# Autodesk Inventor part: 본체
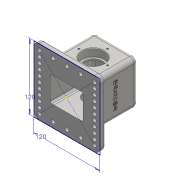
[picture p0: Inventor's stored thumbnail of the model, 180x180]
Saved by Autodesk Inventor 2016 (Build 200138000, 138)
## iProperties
Created: 2018-11
Part Number: 본체
Material: 일반
Document SubType Name: Modeling
Designer: 605-04
Density: 1 g/cm^3
Appearance: 기본값
Author: 605-04
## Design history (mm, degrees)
sketch "스케치1"
  geometry: L1 (-60, 60)-(60, 60); L2 (60, 60)-(60, -60); L3 (60, -60)-(-60, -60); L4 (-60, -60)-(-60, 60); L5 (-60, 60)-(60, -60); L6 (60, 60)-(-60, -60); L7 (-60, 60)-(60, 60); L8 (60, 60)-(60, -60); L9 (60, -60)-(-60, -60); L10 (-60, -60)-(-60, 60); L11 (-60, 60)-(60, -60); L12 (60, 60)-(-60, -60); 1 further point
  constraints: 24 end point, 4 midpoint, 4 parallel, 2 horizontal, 2 perpendicular
  dimensions: "d90" = 120 distance of L2.end L3.end; "d91" = 120 distance of L1.end L2.end
extrude "돌출1" new body sketch "스케치1" distance "d1" = 10; taper "d2" = 0 deg
sketch "스케치2"
  geometry: L1 (40, -40)-(-40, -40); L2 (-40, -40)-(-40, 40); L3 (-40, 40)-(40, 40); L4 (40, 40)-(40, -40); L5 (40, -40)-(-40, 40); L6 (-40, -40)-(40, 40); 1 further point
  constraints: 12 end point, 2 midpoint, 2 parallel, 1 horizontal, 1 perpendicular
  dimensions: "d3" = 80 distance of L2.end L3.end; "d85" = 80 distance of L1.end L2.end
extrude "돌출2" join sketch "스케치2" distance "d4" = 80; taper "d5" = 0 deg
sketch "스케치3"
  geometry: C1 r 7.5 at (0, 0); 1 further point
  constraints: 1 centre point, 1 coincident
  dimensions: "d6" = 15 diameter of C1
extrude "돌출3" join sketch "스케치3" distance "d7" = 5; taper "d8" = 0 deg
sketch "스케치5"
  geometry: L1 (-30, -23)-(30, -23); L2 (30, -23)-(30, 23); L3 (30, 23)-(-30, 23); L4 (-30, 23)-(-30, -23); L5 (-30, -23)-(30, 23); L6 (30, -23)-(-30, 23); 1 further point
  constraints: 12 end point, 2 midpoint, 2 parallel, 1 horizontal, 1 perpendicular
  dimensions: "d9" = 46 distance of L1.end L2.end; "d26" = 60 distance of L2.end L3.end
extrude "돌출4" cut sketch "스케치5" distance "d10" = 80; taper "d11" = 0 deg
sketch "스케치6"
  geometry: L1 (100, -10)-(-20, -10) reference; C1 r 20 at (40, 38); 1 further point
  constraints: 1 centre point
  dimensions: "d12" = 48 distance from line of L1 C1.centre; "d13" = 40 diameter of C1
extrude "돌출5" cut sketch "스케치6" distance "d14" = 14; taper "d15" = 0 deg
sketch "스케치7"
  geometry: C1 r 16.5 at (0, 0); 1 further point
  constraints: 1 centre point
  dimensions: "d16" = 33 diameter of C1
extrude "돌출6" cut sketch "스케치7" distance "d17" = 3; taper "d18" = 0 deg
sketch "스케치8"
  geometry: 2 further points
  constraints: 1 coincident
hole "구멍1" sketch "스케치8" at (0, 0) diameter "d19" = 4.917; stored, may be unused: countersink angle "d23" = 90 deg, drill point angle "d25" = 118 deg; dims "d20" = 12, "d21" = 4, "d22" = 2, "d24" = 17.1
sketch "스케치9" dims "d27" = 52
  geometry: C1 r 16.5 at (40, 38) reference; 3 further points
  constraints: 1 coincident, 1 vertical alignment, 2 other
hole "구멍2" sketch "스케치9" at (40, 64) diameter "d28" = 3.242; stored, may be unused: countersink angle "d32" = 90 deg, drill point angle "d34" = 118 deg; dims "d29" = 8, "d30" = 4, "d31" = 2, "d33" = 10
chamfer "모따기1" distance "d38" = 1; stored, may be unused: second distance "d39" = 2, angle "d40" = 45 deg
fillet "모깎기1" dims "d41" = 0.6
fillet "모깎기3" dims "d43" = 8
fillet "모깎기5" dims "d61" = 10
fillet "모깎기6" dims "d62" = 3
fillet "모깎기7" dims "d80" = 3
sketch "스케치12"
  geometry: L1 (82, -82)-(-18, -82) reference; 3 further points
  constraints: 1 midpoint, 1 vertical alignment, 1 other
  dimensions: "d82" = 48 distance from line of L1 point (32, -34)
feature "엠보싱1" sketch "스케치12" dims "d83" = 0.5, "d84" = 0, "d90" = 120, "d91" = 120
sketch "스케치13"
  geometry: A1 r 10 centre (-50, 50) between (-50, 60) and (-60, 50) reference; A2 r 7 centre (-50, -50) between (-57, -50) and (-50, -57) reference; A3 r 10 centre (50, -50) between (50, -60) and (60, -50) reference; A4 r 10 centre (50, 50) between (60, 50) and (50, 60) reference; 16 further points
  constraints: 3 coincident
  dimensions: "d92" = 25 distance of point (-50, 50) point (-25, 50); "d93" = 25 distance of point (50, 50) point (25, 50); "d94" = 10 distance of point (-50, 30) point (-50, 40); "d95" = 10 distance of point (-50, 30) point (-50, 20); "d96" = 10 distance of point (-50, 20) point (-50, 10); "d97" = 10 distance of point (-50, 50) point (-50, 40); "d98" = 10 distance of point (-50, 0) point (-50, 10); "d99" = 10 distance of point (-50, 0) point (-50, -10); "d100" = 10 distance of point (-50, -20) point (-50, -10); "d101" = 10 distance of point (-50, -20) point (-50, -30); "d102" = 10 distance of point (-50, -30) point (-50, -40); "d103" = 10 distance of point (-50, -40) point (-50, -50)
hole "구멍4" sketch "스케치13" at (50, 50), (25, 50), (0, 50), (-25, 50), (-50, 50), (-50, 40), (-50, 30), (-50, 20), (-50, 10), (-50, 0), (-50, -10), (-50, -20)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 diameter "d104" = 6.6; stored, may be unused: countersink angle "d108" = 90 deg, drill point angle "d110" = 0 deg; dims "d105" = 8, "d106" = 4, "d107" = 2, "d109" = 10
node "솔리드1"
mirror "대칭1"
mirror "대칭2"
pattern_circular "원형 패턴1" dims angle "d36" = 360 deg
mirror "대칭3"
mirror "대칭6"
mirror "대칭7"
